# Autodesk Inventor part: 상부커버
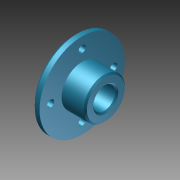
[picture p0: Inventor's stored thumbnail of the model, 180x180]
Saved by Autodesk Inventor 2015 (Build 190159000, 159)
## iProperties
Created: 2025-08
Part Number: 상부커버
Material: 일반
Document SubType Name: Modeling
Designer: USER
Density: 1 g/cm^3
Appearance: 기본값
Author: USER
Author: jhkim
Creation Date: 2025-08-05
Sending System: Autodesk Inventor 2026
Preprocessor: ST-DEVELOPER v20.1
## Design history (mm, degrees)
node "상부커버1"
node "솔리드1"
node "기준1"
